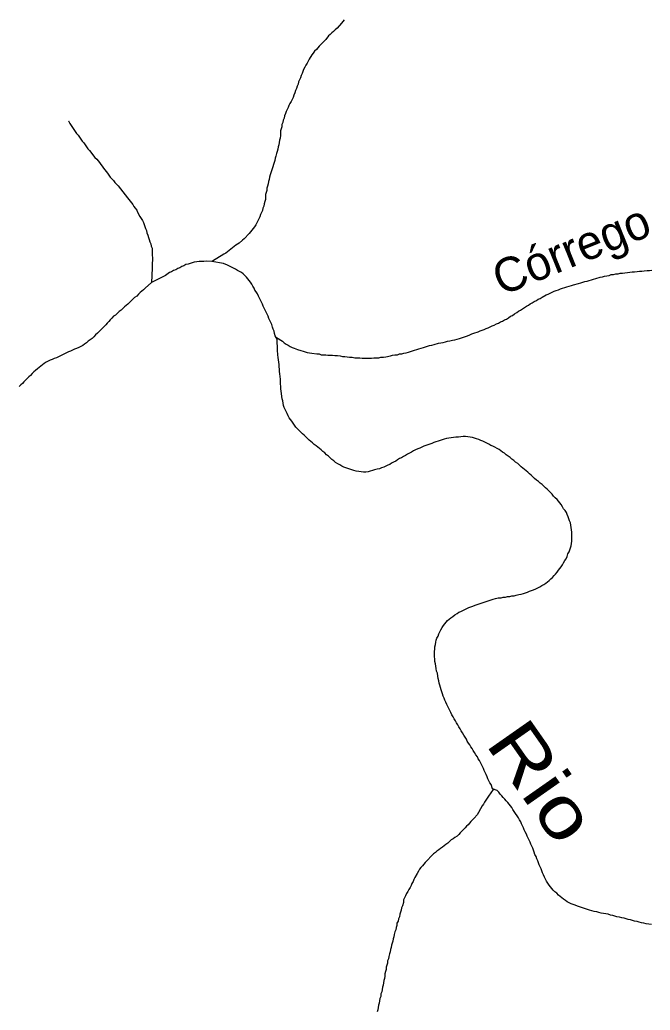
# Model space of a CAD drawing. Extents: x 652.3 to 678, y 7316.9 to 7344.9.
# Drawn here: x 665.23 to 666.71, y 7330.429 to 7332.753 of the extents above; entities that cross this region are included whole.
import ezdxf
from ezdxf.enums import TextEntityAlignment as Align

# ---------------------------------------------------------------- set-up
doc = ezdxf.new("R2010")
doc.units = 0
doc.header["$LTSCALE"] = 0.032
doc.layers.add('61', color=7, linetype='Continuous')
doc.layers.add('7', color=7, linetype='Continuous', lineweight=25)

msp = doc.modelspace()

# ---------------------------------------------------------------- linework, layer by layer
at = {"layer": '7'}
msp.add_line((665.6815, 7332.1864), (665.6812, 7332.1863), dxfattribs=at)
for points in [[(665.9919, 7332.7534), (665.9852, 7332.7456), (665.9748, 7332.7337), (665.9708, 7332.7297), (665.9669, 7332.7257), (665.9629, 7332.7226), (665.9589, 7332.7186), (665.9549, 7332.7154), (665.9486, 7332.7074), (665.9446, 7332.7035), (665.9326, 7332.6915), (665.9263, 7332.6836), (665.9223, 7332.6796), (665.9191, 7332.6748), (665.9159, 7332.6708), (665.9096, 7332.6613), (665.9072, 7332.6565), (665.9048, 7332.6517), (665.9016, 7332.647), (665.8992, 7332.6422), (665.896, 7332.6366), (665.8929, 7332.6271), (665.8905, 7332.6223), (665.8889, 7332.6175), (665.8841, 7332.608), (665.8833, 7332.6024), (665.8809, 7332.5976), (665.8801, 7332.5921), (665.8777, 7332.5873), (665.8761, 7332.5817), (665.8738, 7332.5769), (665.8722, 7332.5714), (665.8674, 7332.5618), (665.8642, 7332.5571), (665.8618, 7332.5523), (665.8602, 7332.5475), (665.8555, 7332.538), (665.8539, 7332.5332), (665.8515, 7332.5284), (665.8507, 7332.5228), (665.8483, 7332.5181), (665.8475, 7332.5125), (665.8451, 7332.5077), (665.8451, 7332.5021), (665.8435, 7332.4974), (665.8419, 7332.4926), (665.8419, 7332.4815), (665.8411, 7332.4759), (665.8395, 7332.4711), (665.8387, 7332.4655), (665.838, 7332.46), (665.8364, 7332.4552), (665.8356, 7332.4496), (665.834, 7332.4441), (665.8324, 7332.4393), (665.8316, 7332.4337), (665.83, 7332.4289), (665.8292, 7332.4234), (665.8276, 7332.4186), (665.826, 7332.4138), (665.8244, 7332.4083), (665.8228, 7332.4035), (665.8181, 7332.3892), (665.8165, 7332.3844), (665.8157, 7332.3788), (665.8141, 7332.374), (665.8133, 7332.3685), (665.8117, 7332.3629), (665.8101, 7332.3581), (665.8101, 7332.3526), (665.8069, 7332.343), (665.8069, 7332.3319), (665.8053, 7332.3271), (665.8037, 7332.3215), (665.8029, 7332.316), (665.8006, 7332.3112), (665.7998, 7332.3056), (665.795, 7332.2961), (665.7934, 7332.2913), (665.7886, 7332.2817), (665.787, 7332.277), (665.7846, 7332.2722), (665.7815, 7332.2674), (665.7751, 7332.2595), (665.7719, 7332.2555), (665.7687, 7332.2515), (665.7568, 7332.2396), (665.7528, 7332.2364), (665.7449, 7332.2292), (665.7377, 7332.2245), (665.7337, 7332.2213), (665.7297, 7332.2181), (665.7258, 7332.2149), (665.7218, 7332.2117), (665.7178, 7332.2085), (665.7138, 7332.2054), (665.709, 7332.203), (665.6828, 7332.1871), (665.6815, 7332.1864)], [(665.3446, 7332.5165), (665.3448, 7332.5161), (665.3462, 7332.5133), (665.3478, 7332.5101), (665.351, 7332.5053), (665.3605, 7332.491), (665.3637, 7332.4862), (665.3669, 7332.4823), (665.3701, 7332.4783), (665.3733, 7332.4735), (665.3765, 7332.4687), (665.3804, 7332.4648), (665.3868, 7332.4552), (665.39, 7332.4504), (665.394, 7332.4465), (665.4067, 7332.4305), (665.4107, 7332.4266), (665.417, 7332.4186), (665.4202, 7332.4138), (665.4234, 7332.4098), (665.4266, 7332.4051), (665.4361, 7332.3931), (665.4393, 7332.3884), (665.4425, 7332.3844), (665.4465, 7332.3804), (665.4505, 7332.3764), (665.4536, 7332.3717), (665.4576, 7332.3677), (665.4608, 7332.3637), (665.4831, 7332.3359), (665.4863, 7332.3319), (665.4958, 7332.3199), (665.4982, 7332.3152), (665.5014, 7332.3112), (665.5046, 7332.3064), (665.5069, 7332.3016), (665.5117, 7332.2921), (665.5149, 7332.2873), (665.5181, 7332.2825), (665.5205, 7332.2778), (665.5237, 7332.2682), (665.5252, 7332.2634), (665.5276, 7332.2587), (665.5284, 7332.2531), (665.5308, 7332.2483), (665.5324, 7332.2428), (665.534, 7332.238), (665.5356, 7332.2324), (665.538, 7332.2276), (665.5388, 7332.2221), (665.5412, 7332.2173), (665.5412, 7332.2006), (665.542, 7332.195), (665.542, 7332.1894), (665.5412, 7332.1823), (665.5412, 7332.1703), (665.5396, 7332.1369)], [(665.9056, 7331.7709), (665.9016, 7331.7749), (665.8976, 7331.7781), (665.8936, 7331.7813), (665.8897, 7331.7852), (665.8857, 7331.7892), (665.8817, 7331.7932), (665.8785, 7331.7972), (665.8753, 7331.8019), (665.8722, 7331.8067), (665.869, 7331.8115), (665.8658, 7331.8155), (665.8626, 7331.8194), (665.8602, 7331.8242), (665.8578, 7331.829), (665.8555, 7331.8338), (665.8531, 7331.8385), (665.8507, 7331.8433), (665.8491, 7331.8481), (665.8483, 7331.8537), (665.8475, 7331.8592), (665.8459, 7331.864), (665.8451, 7331.8696), (665.8443, 7331.8759), (665.8435, 7331.8815), (665.8427, 7331.8871), (665.8427, 7331.8927), (665.8419, 7331.899), (665.8419, 7331.9046), (665.8419, 7331.9102), (665.8411, 7331.9165), (665.8403, 7331.9221), (665.8395, 7331.9277), (665.8395, 7331.9332), (665.8387, 7331.9388), (665.8387, 7331.9444), (665.838, 7331.9499), (665.8372, 7331.9555), (665.8364, 7331.9611), (665.8356, 7331.9667), (665.8348, 7331.9778), (665.834, 7332.004), (665.83, 7332.012), (665.8284, 7332.0168), (665.8276, 7332.0223), (665.8252, 7332.0271), (665.8236, 7332.0319), (665.822, 7332.0383), (665.8196, 7332.043), (665.8173, 7332.0478), (665.8149, 7332.0526), (665.8133, 7332.0574), (665.8109, 7332.0621), (665.8085, 7332.0669), (665.8061, 7332.0717), (665.8037, 7332.0765), (665.8013, 7332.0812), (665.7998, 7332.086), (665.7974, 7332.0908), (665.795, 7332.0956), (665.7926, 7332.1003), (665.7902, 7332.1051), (665.7878, 7332.1099), (665.7854, 7332.1146), (665.7823, 7332.1186), (665.7807, 7332.1234), (665.7775, 7332.1282), (665.7751, 7332.1329), (665.7719, 7332.1377), (665.7687, 7332.1417), (665.7655, 7332.1457), (665.7624, 7332.1497), (665.7584, 7332.1536), (665.7544, 7332.1568), (665.7504, 7332.16), (665.7457, 7332.1624), (665.7409, 7332.1648), (665.7369, 7332.168), (665.7321, 7332.1703), (665.7273, 7332.1727), (665.7226, 7332.1751), (665.7178, 7332.1775), (665.7083, 7332.1815), (665.6812, 7332.1863), (665.6677, 7332.1871), (665.6621, 7332.1863), (665.6565, 7332.1863), (665.651, 7332.1863), (665.6454, 7332.1855), (665.6398, 7332.1847), (665.635, 7332.1831), (665.6303, 7332.1815), (665.6255, 7332.1799), (665.6199, 7332.1791), (665.6152, 7332.1759), (665.6104, 7332.1743), (665.6056, 7332.1711), (665.6008, 7332.1696), (665.5961, 7332.1664), (665.5913, 7332.1648), (665.5865, 7332.1616)], [(665.5865, 7332.1616), (665.5817, 7332.16), (665.5722, 7332.1536), (665.5396, 7332.1369)], [(666.5827, 7332.1465), (666.5923, 7332.1497), (666.5978, 7332.1505), (666.6026, 7332.152), (666.6082, 7332.1528), (666.6137, 7332.1536), (666.6185, 7332.1552), (666.6241, 7332.1552), (666.6289, 7332.1568), (666.6344, 7332.1568), (666.6392, 7332.1584), (666.6448, 7332.1584), (666.6503, 7332.1592), (666.6567, 7332.16), (666.6679, 7332.1616), (666.6734, 7332.1616), (666.679, 7332.1624), (666.6846, 7332.1632), (666.6901, 7332.1632), (666.6957, 7332.164), (666.7029, 7332.1648), (666.7084, 7332.1648), (666.714, 7332.1656)], [(665.5396, 7332.1369), (665.5244, 7332.1234), (665.5205, 7332.1194), (665.5165, 7332.1162), (665.5125, 7332.1131), (665.5085, 7332.1091), (665.5046, 7332.1051), (665.4998, 7332.1019), (665.4958, 7332.0979), (665.4918, 7332.094), (665.4878, 7332.09), (665.4839, 7332.086), (665.4799, 7332.0828), (665.4759, 7332.0796), (665.4719, 7332.0757), (665.468, 7332.0717), (665.4632, 7332.0685), (665.4592, 7332.0645), (665.4552, 7332.0605), (665.4505, 7332.0574), (665.4465, 7332.0534), (665.4425, 7332.0494), (665.4393, 7332.0454), (665.4353, 7332.0414), (665.4321, 7332.0375), (665.4282, 7332.0335), (665.4242, 7332.0295), (665.4202, 7332.0255), (665.4162, 7332.0216), (665.4123, 7332.0176), (665.4083, 7332.0136), (665.4043, 7332.0096), (665.4003, 7332.0056), (665.3955, 7332.0025), (665.3908, 7331.9993), (665.3868, 7331.9953), (665.382, 7331.9921), (665.378, 7331.9889), (665.3733, 7331.9865), (665.3685, 7331.9842), (665.3637, 7331.9818), (665.3589, 7331.9802), (665.3542, 7331.9778), (665.3494, 7331.9754), (665.3446, 7331.9738), (665.3398, 7331.9714), (665.3351, 7331.969), (665.3303, 7331.9674), (665.3255, 7331.9643), (665.3208, 7331.9627), (665.316, 7331.9603), (665.3112, 7331.9587), (665.3064, 7331.9563), (665.3017, 7331.9547), (665.2969, 7331.9523), (665.2921, 7331.9499), (665.2873, 7331.9468), (665.2834, 7331.9436), (665.2794, 7331.9404), (665.2754, 7331.9372), (665.2714, 7331.934), (665.2674, 7331.93), (665.2635, 7331.9269), (665.2595, 7331.9229), (665.2555, 7331.9189), (665.2515, 7331.9157), (665.2475, 7331.9117), (665.2436, 7331.9078), (665.2396, 7331.9038), (665.2364, 7331.8998), (665.2324, 7331.8966), (665.2285, 7331.8927)], [(665.97, 7331.9651), (665.9756, 7331.9651), (665.982, 7331.9643), (665.9875, 7331.9635), (665.9931, 7331.9635), (665.9987, 7331.9627), (666.0042, 7331.9619), (666.0106, 7331.9619), (666.017, 7331.9603), (666.0281, 7331.9603), (666.0337, 7331.9595), (666.056, 7331.9595), (666.0615, 7331.9603), (666.0727, 7331.9603), (666.0775, 7331.9619), (666.0838, 7331.9619), (666.0894, 7331.9627), (666.1005, 7331.9643), (666.1053, 7331.9659), (666.1109, 7331.9667), (666.1164, 7331.9674), (666.1212, 7331.969), (666.1268, 7331.969), (666.1316, 7331.9706), (666.1371, 7331.9714), (666.1427, 7331.973), (666.157, 7331.9778), (666.1618, 7331.9794), (666.1666, 7331.981), (666.1777, 7331.9842), (666.1825, 7331.9857), (666.192, 7331.9889), (666.1976, 7331.9897), (666.2032, 7331.9913), (666.2127, 7331.9945), (666.2239, 7331.9961), (666.2294, 7331.9977), (666.2342, 7331.9993), (666.2398, 7332.0001), (666.2461, 7332.0017), (666.2517, 7332.0025), (666.2565, 7332.004), (666.2621, 7332.0056), (666.2668, 7332.0072), (666.2716, 7332.0088), (666.2811, 7332.012), (666.2867, 7332.0136), (666.2915, 7332.016), (666.2963, 7332.0176), (666.3058, 7332.0208), (666.3106, 7332.0231), (666.3201, 7332.0263), (666.3249, 7332.0287), (666.3297, 7332.0303), (666.3345, 7332.0327), (666.3392, 7332.0351), (666.344, 7332.0367), (666.3488, 7332.0399), (666.3536, 7332.0414), (666.3583, 7332.0446), (666.3631, 7332.0462), (666.3679, 7332.0494), (666.3727, 7332.051), (666.3774, 7332.0542), (666.3822, 7332.0574), (666.387, 7332.0597), (666.3917, 7332.0629), (666.3965, 7332.0661), (666.4005, 7332.0693), (666.4053, 7332.0717), (666.4101, 7332.0749), (666.4148, 7332.078), (666.4196, 7332.0812), (666.4244, 7332.0836), (666.4284, 7332.0868), (666.4331, 7332.0892), (666.4379, 7332.0924), (666.4427, 7332.0948), (666.4467, 7332.0979), (666.4514, 7332.0995), (666.4562, 7332.1027), (666.4657, 7332.1075), (666.4705, 7332.1091), (666.4848, 7332.1162), (666.4896, 7332.1178), (666.4944, 7332.1194), (666.4992, 7332.1218), (666.5039, 7332.1234), (666.5095, 7332.125), (666.5143, 7332.1266), (666.5199, 7332.1282), (666.5254, 7332.1298), (666.5302, 7332.1314), (666.5413, 7332.1345), (666.5469, 7332.1361), (666.5565, 7332.1393), (666.562, 7332.1401), (666.5668, 7332.1417), (666.5724, 7332.1433), (666.5771, 7332.1449), (666.5827, 7332.1465)], [(665.8324, 7332.008), (665.8467, 7331.9993), (665.8507, 7331.9953), (665.8555, 7331.9921), (665.8602, 7331.9897), (665.865, 7331.9865), (665.8698, 7331.9842), (665.8746, 7331.9826), (665.8817, 7331.9794), (665.8897, 7331.977), (665.8952, 7331.9754), (665.9048, 7331.9722), (665.9104, 7331.9714), (665.9159, 7331.9706), (665.9271, 7331.969), (665.9326, 7331.969), (665.9374, 7331.9674), (665.9486, 7331.9674), (665.9533, 7331.9659), (665.9645, 7331.9659), (665.97, 7331.9651)], [(666.3854, 7331.7224), (666.3814, 7331.7264), (666.3766, 7331.7295), (666.3719, 7331.7327), (666.3679, 7331.7359), (666.3631, 7331.7383), (666.3591, 7331.7415), (666.3551, 7331.7447), (666.3504, 7331.747), (666.3456, 7331.7502), (666.3408, 7331.7526), (666.3361, 7331.7542), (666.3313, 7331.7574), (666.3265, 7331.7598), (666.3217, 7331.7622), (666.317, 7331.7645), (666.3122, 7331.7661), (666.3074, 7331.7685), (666.3026, 7331.7701), (666.2979, 7331.7717), (666.2931, 7331.7733), (666.2875, 7331.7741), (666.2819, 7331.7749), (666.2764, 7331.7757), (666.2708, 7331.7757), (666.2652, 7331.7749), (666.2597, 7331.7741), (666.2541, 7331.7741), (666.2485, 7331.7733), (666.243, 7331.7725), (666.2374, 7331.7717), (666.2318, 7331.7709), (666.2262, 7331.7693), (666.2215, 7331.7677), (666.2167, 7331.7661), (666.2119, 7331.7645), (666.2071, 7331.763), (666.2024, 7331.7614), (666.1976, 7331.759), (666.1928, 7331.7574), (666.1881, 7331.7558), (666.1833, 7331.7542), (666.1785, 7331.7526), (666.1737, 7331.7502), (666.169, 7331.7478), (666.1642, 7331.7462), (666.1594, 7331.7439), (666.1546, 7331.7415), (666.1499, 7331.7383), (666.1451, 7331.7359), (666.1403, 7331.7335), (666.1355, 7331.7311), (666.1308, 7331.7287), (666.126, 7331.7256), (666.1212, 7331.724), (666.1164, 7331.7208), (666.1125, 7331.7176), (666.1077, 7331.7152), (666.1029, 7331.7128), (666.0989, 7331.7096), (666.0942, 7331.7081), (666.0894, 7331.7057), (666.0846, 7331.7033), (666.079, 7331.7017), (666.0743, 7331.6993), (666.0687, 7331.6985), (666.0631, 7331.6969), (666.0584, 7331.6953), (666.0528, 7331.6937), (666.048, 7331.6921), (666.0424, 7331.6913), (666.0369, 7331.6913), (666.0313, 7331.6921), (666.0257, 7331.6929), (666.0194, 7331.6937), (666.0146, 7331.6953), (666.0098, 7331.6969), (666.005, 7331.6985), (666.0003, 7331.7001), (665.9955, 7331.7017), (665.9907, 7331.7033), (665.9859, 7331.7057), (665.9812, 7331.7088), (665.9764, 7331.7112), (665.9716, 7331.7144), (665.9676, 7331.7184), (665.9629, 7331.7216), (665.9589, 7331.7256), (665.9549, 7331.7295), (665.9501, 7331.7327), (665.9462, 7331.7367), (665.9414, 7331.7399), (665.9374, 7331.7439), (665.9334, 7331.747), (665.9295, 7331.7502), (665.9255, 7331.7534), (665.9215, 7331.7566), (665.9175, 7331.7606), (665.9135, 7331.7638), (665.9096, 7331.7669), (665.9056, 7331.7709)], [(666.2987, 7331.3794), (666.3034, 7331.381), (666.3082, 7331.3826), (666.313, 7331.3842), (666.3178, 7331.3858), (666.3225, 7331.3874), (666.3273, 7331.389), (666.3321, 7331.3906), (666.3368, 7331.3922), (666.3416, 7331.3938), (666.3472, 7331.3953), (666.3528, 7331.3969), (666.3599, 7331.3969), (666.3647, 7331.3985), (666.3703, 7331.3985), (666.375, 7331.4001), (666.3806, 7331.4001), (666.3854, 7331.4017), (666.391, 7331.4017), (666.3957, 7331.4033), (666.4013, 7331.4041), (666.4069, 7331.4049), (666.4124, 7331.4065), (666.4172, 7331.4081), (666.422, 7331.4097), (666.4268, 7331.4121), (666.4315, 7331.4136), (666.4363, 7331.4152), (666.4411, 7331.4176), (666.4459, 7331.42), (666.4506, 7331.4224), (666.4554, 7331.4256), (666.4602, 7331.428), (666.465, 7331.4312), (666.4689, 7331.4343), (666.4729, 7331.4375), (666.4769, 7331.4415), (666.4809, 7331.4447), (666.4848, 7331.4487), (666.488, 7331.4526), (666.4912, 7331.4566), (666.4944, 7331.4614), (666.4976, 7331.4654), (666.5008, 7331.4693), (666.5039, 7331.4741), (666.5063, 7331.4789), (666.5095, 7331.4845), (666.5127, 7331.4884), (666.5151, 7331.494), (666.5167, 7331.4996), (666.5199, 7331.5044), (666.5214, 7331.5091), (666.523, 7331.5139), (666.5246, 7331.5187), (666.5254, 7331.5242), (666.5262, 7331.5298), (666.5262, 7331.5354), (666.5262, 7331.5449), (666.5262, 7331.5505), (666.5254, 7331.5561), (666.5246, 7331.5616), (666.5238, 7331.5672), (666.523, 7331.5728), (666.5207, 7331.5776), (666.5191, 7331.5823), (666.5175, 7331.5871), (666.5151, 7331.5919), (666.5135, 7331.5967), (666.5103, 7331.6014), (666.5063, 7331.6054), (666.5039, 7331.6102), (666.5008, 7331.6158), (666.4976, 7331.6197), (666.4944, 7331.6237), (666.4912, 7331.6277), (666.4872, 7331.6317), (666.4833, 7331.6356), (666.4801, 7331.6396), (666.4761, 7331.6436), (666.4721, 7331.6476), (666.4681, 7331.6516), (666.4642, 7331.6547), (666.4602, 7331.6587), (666.4562, 7331.6627), (666.4514, 7331.6659), (666.4474, 7331.6699), (666.4427, 7331.673), (666.4387, 7331.677), (666.4347, 7331.681), (666.4307, 7331.6842), (666.4268, 7331.6874), (666.4228, 7331.6913), (666.4188, 7331.6945), (666.4148, 7331.6977), (666.4108, 7331.7009), (666.4069, 7331.7041), (666.4029, 7331.7081), (666.3989, 7331.712), (666.3941, 7331.7152), (666.3902, 7331.7192), (666.3854, 7331.7224)], [(666.34, 7330.9482), (666.3368, 7330.9585), (666.3337, 7330.9625), (666.3313, 7330.9673), (666.3289, 7330.972), (666.3273, 7330.9768), (666.3249, 7330.9816), (666.3225, 7330.9864), (666.3201, 7330.9911), (666.3185, 7330.9959), (666.3162, 7331.0007), (666.3138, 7331.0055), (666.3114, 7331.0102), (666.309, 7331.015), (666.3058, 7331.019), (666.3042, 7331.0238), (666.301, 7331.0285), (666.2979, 7331.0333), (666.2947, 7331.0381), (666.2923, 7331.0429), (666.2891, 7331.0468), (666.2867, 7331.0516), (666.2835, 7331.0556), (666.2804, 7331.0604), (666.2788, 7331.0651), (666.2756, 7331.0699), (666.2724, 7331.0747), (666.2692, 7331.0795), (666.266, 7331.0842), (666.2636, 7331.089), (666.2605, 7331.0938), (666.2581, 7331.0986), (666.2549, 7331.1033), (666.2533, 7331.1081), (666.2501, 7331.1129), (666.2477, 7331.1177), (666.2445, 7331.1224), (666.2422, 7331.1272), (666.2398, 7331.132), (666.2374, 7331.1367), (666.235, 7331.1415), (666.2326, 7331.1463), (666.2302, 7331.1519), (666.2278, 7331.1566), (666.2262, 7331.1614), (666.2239, 7331.1662), (666.2223, 7331.171), (666.2207, 7331.1757), (666.2191, 7331.1805), (666.2175, 7331.1861), (666.2159, 7331.1917), (666.2143, 7331.1964), (666.2135, 7331.202), (666.2119, 7331.2076), (666.2111, 7331.2131), (666.2103, 7331.2195), (666.2087, 7331.2243), (666.2079, 7331.2306), (666.2064, 7331.2362), (666.2056, 7331.2418), (666.2048, 7331.2473), (666.2048, 7331.2529), (666.204, 7331.2593), (666.204, 7331.2649), (666.204, 7331.2704), (666.2048, 7331.276), (666.2048, 7331.2816), (666.2056, 7331.2871), (666.2064, 7331.2927), (666.2079, 7331.2975), (666.2095, 7331.3023), (666.2119, 7331.307), (666.2135, 7331.3118), (666.2159, 7331.3166), (666.2183, 7331.3213), (666.2215, 7331.3269), (666.2247, 7331.3317), (666.2278, 7331.3357), (666.231, 7331.3396), (666.2342, 7331.3436), (666.2382, 7331.3468), (666.2422, 7331.35), (666.2469, 7331.3532), (666.2517, 7331.3564), (666.2565, 7331.3595), (666.2605, 7331.3627), (666.2652, 7331.3643), (666.27, 7331.3667), (666.2748, 7331.3691), (666.2796, 7331.3715), (666.2843, 7331.3739), (666.2891, 7331.3755), (666.2939, 7331.377), (666.2987, 7331.3794)], [(666.34, 7330.9482), (666.3416, 7330.9466), (666.3305, 7330.9315), (666.3273, 7330.9267), (666.3209, 7330.9171), (666.3185, 7330.9124), (666.3154, 7330.9084), (666.3114, 7330.9012), (666.3066, 7330.8925), (666.3034, 7330.8877), (666.2971, 7330.8797), (666.2931, 7330.8758), (666.2891, 7330.8718), (666.2827, 7330.8638), (666.2788, 7330.8606), (666.2756, 7330.8567), (666.2716, 7330.8527), (666.2636, 7330.8447), (666.2605, 7330.8408), (666.2565, 7330.8376), (666.2517, 7330.8344), (666.2477, 7330.8312), (666.243, 7330.8288), (666.239, 7330.8248), (666.235, 7330.8209), (666.2302, 7330.8177), (666.2262, 7330.8145), (666.2223, 7330.8113), (666.2175, 7330.8081), (666.2135, 7330.8049), (666.2095, 7330.8018)], [(666.3719, 7330.9203), (666.3687, 7330.9243), (666.3647, 7330.9283), (666.3615, 7330.9323), (666.3575, 7330.9362), (666.3544, 7330.9402), (666.3504, 7330.9442), (666.34, 7330.9482)], [(666.7132, 7330.6299), (666.7068, 7330.6307), (666.7005, 7330.6315), (666.6949, 7330.6331), (666.6893, 7330.6339), (666.6838, 7330.6355), (666.679, 7330.6371), (666.6734, 7330.6379), (666.6686, 7330.6394), (666.6639, 7330.641), (666.6583, 7330.6418), (666.6535, 7330.6434), (666.6488, 7330.645), (666.6432, 7330.6458), (666.6376, 7330.6474), (666.632, 7330.6482), (666.6273, 7330.6498), (666.6225, 7330.6514), (666.6169, 7330.6522), (666.6114, 7330.6538), (666.6058, 7330.6546), (666.6002, 7330.6554), (666.5946, 7330.6562), (666.5891, 7330.6577), (666.5843, 7330.6593), (666.5787, 7330.6601), (666.5732, 7330.6617), (666.5676, 7330.6633), (666.5628, 7330.6649), (666.558, 7330.6665), (666.5533, 7330.6681), (666.5485, 7330.6697), (666.5437, 7330.6713), (666.539, 7330.6729), (666.5342, 7330.6752), (666.5294, 7330.6768), (666.5246, 7330.6784), (666.5199, 7330.6808), (666.5151, 7330.6832), (666.5111, 7330.6864), (666.5063, 7330.6896), (666.5024, 7330.6928), (666.4984, 7330.6959), (666.4944, 7330.6991), (666.4904, 7330.7031), (666.4864, 7330.7063), (666.4825, 7330.7103), (666.4793, 7330.7142), (666.4761, 7330.7182), (666.4729, 7330.7222), (666.4697, 7330.727), (666.4665, 7330.7317), (666.4642, 7330.7365), (666.4618, 7330.7413), (666.4594, 7330.7461), (666.457, 7330.7508), (666.4554, 7330.7556), (666.4538, 7330.7604), (666.4514, 7330.7652), (666.449, 7330.7699), (666.4474, 7330.7747), (666.4459, 7330.7795), (666.4435, 7330.7843), (666.4419, 7330.7898), (666.4395, 7330.7946), (666.4379, 7330.7994), (666.4363, 7330.8041), (666.4347, 7330.8089), (666.4323, 7330.8137), (666.4299, 7330.8185), (666.4284, 7330.8232), (666.426, 7330.828), (666.4236, 7330.8328), (666.4212, 7330.8376), (666.4196, 7330.8423), (666.4164, 7330.8471), (666.414, 7330.8519), (666.4124, 7330.8567), (666.4101, 7330.8614), (666.4077, 7330.8662), (666.4061, 7330.871), (666.4029, 7330.8758), (666.4005, 7330.8805), (666.3973, 7330.8853), (666.3941, 7330.8901), (666.391, 7330.8949), (666.3878, 7330.8996), (666.3854, 7330.9044), (666.3822, 7330.9084), (666.379, 7330.9124), (666.3758, 7330.9163), (666.3719, 7330.9203)], [(666.2095, 7330.8018), (666.2056, 7330.7986), (666.2016, 7330.7954), (666.1817, 7330.7755), (666.1753, 7330.7675), (666.1713, 7330.7636), (666.1682, 7330.7596), (666.1658, 7330.7548), (666.1626, 7330.75), (666.1578, 7330.7405), (666.1554, 7330.7357), (666.1538, 7330.7309), (666.1507, 7330.7262), (666.1491, 7330.7214), (666.1467, 7330.7166), (666.1435, 7330.7119), (666.1411, 7330.7071), (666.1379, 7330.7023), (666.1355, 7330.6975), (666.1308, 7330.688), (666.1308, 7330.6816), (666.1284, 7330.6737), (666.126, 7330.6689), (666.1252, 7330.6633), (666.122, 7330.6538), (666.1212, 7330.6482), (666.1188, 7330.6434), (666.118, 7330.6379), (666.1156, 7330.6331), (666.1156, 7330.6275), (666.1133, 7330.6227), (666.1125, 7330.6172), (666.1109, 7330.6124), (666.1093, 7330.6068), (666.1085, 7330.6012), (666.1069, 7330.5965), (666.1061, 7330.5909), (666.1029, 7330.5814), (666.1021, 7330.5758), (666.1005, 7330.571), (666.0997, 7330.5654), (666.0981, 7330.5607), (666.0965, 7330.5551), (666.0958, 7330.5495), (666.0934, 7330.5448), (666.0934, 7330.5392), (666.0918, 7330.5344), (666.0902, 7330.5296), (666.0902, 7330.5241), (666.0886, 7330.5193), (666.087, 7330.5145), (666.087, 7330.5089), (666.0862, 7330.5034), (666.0846, 7330.4986), (666.083, 7330.4875), (666.0814, 7330.4827), (666.0806, 7330.4771), (666.0798, 7330.4716), (666.0775, 7330.4668), (666.0775, 7330.4612), (666.0751, 7330.4564), (666.0743, 7330.4509), (666.0735, 7330.4453), (666.0719, 7330.4405), (666.0711, 7330.435), (666.0703, 7330.4294), (666.0687, 7330.4246)]]:
    msp.add_lwpolyline(points, dxfattribs=at)

# ---------------------------------------------------------------- texts
at = {"layer": '61'}
msp.add_text('Córrego', height=0.08, rotation=22.049, dxfattribs=at).set_placement((666.5396, 7332.1774), align=Align.CENTER)
at = {"layer": '61', "width": 1.25}
msp.add_text('Rio', height=0.12, rotation=305.016, dxfattribs=at).set_placement((666.4075, 7330.9312), align=Align.CENTER)

doc.saveas('drawing.dxf')
